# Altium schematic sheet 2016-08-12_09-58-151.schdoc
size 281 x 111 mm; SheetNumber: 1; SheetTotal: 1
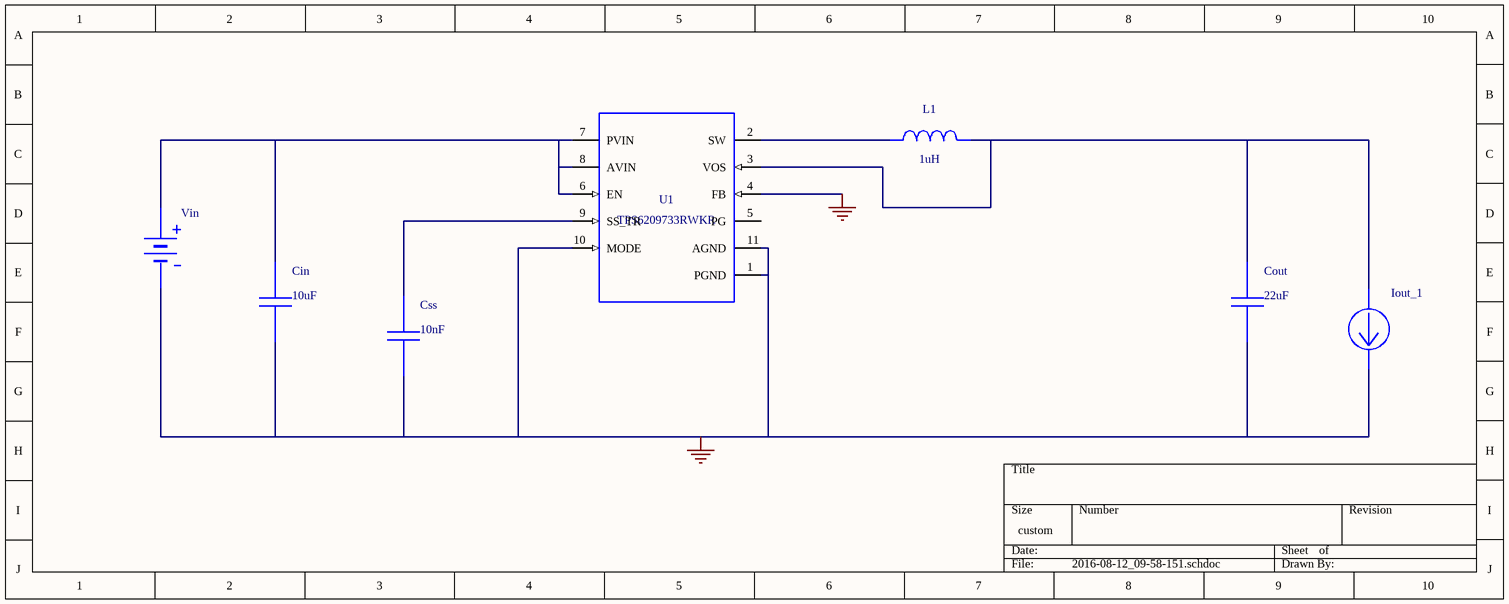
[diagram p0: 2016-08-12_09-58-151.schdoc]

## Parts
Cin  value 10uF  (hidden comment: GRM188R60J106ME47D)
Cout  value 22uF  (hidden comment: GRM21BR60J226ME39L)
Css  value 10nF  (hidden comment: GRM033R61A103KA01D)
Iout_1  WB_CURRENT_LOAD  (value not drawn)
L1  value 1uH  (hidden comment: SRN6045-1R0Y)
U1  TPS6209733RWKR
Vin  WB_BATTERY  (value not drawn)

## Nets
0: Cin.2 Cout.2 Css.2 Iout_1.2(-) U1.1(PGND) U1.4(FB) U1.10(MODE) U1.11(AGND) Vin.2(-)
NetCin_1: Cin.1 U1.6(EN) U1.7(PVIN) U1.8(AVIN) Vin.1(+)
NetCout_1: Cout.1 Iout_1.1(+) L1.2 U1.3(VOS)
NetCss_1: Css.1 U1.9(SS_TR)
NetL1_1: L1.1 U1.2(SW)

Not connected (* = marked no-connect by the designer): U1 5(PG)

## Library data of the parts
Cin = GRM188R60J106ME47D: GRM188R60J106ME4; Manufacturer Name: MuRata
Cout = GRM21BR60J226ME39L: GRM21BR60J226ME3; Manufacturer Name: MuRata
Css = GRM033R61A103KA01D: GRM033R61A103KA0; Manufacturer Name: MuRata
L1 = SRN6045-1R0Y: Manufacturer Name: Bourns
U1 = TPS6209733RWKR: Manufacturer Name: Texas Instruments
